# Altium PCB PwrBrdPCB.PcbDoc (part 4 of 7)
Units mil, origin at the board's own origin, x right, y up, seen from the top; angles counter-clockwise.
Board outline 8000 x 5500 mil, 4 copper layers (Top Layer, Internal 1, Internal 2, Bottom Layer), stack 61.834 mil thick; 682 components, 380 nets, 1899 pads, 766 vias.
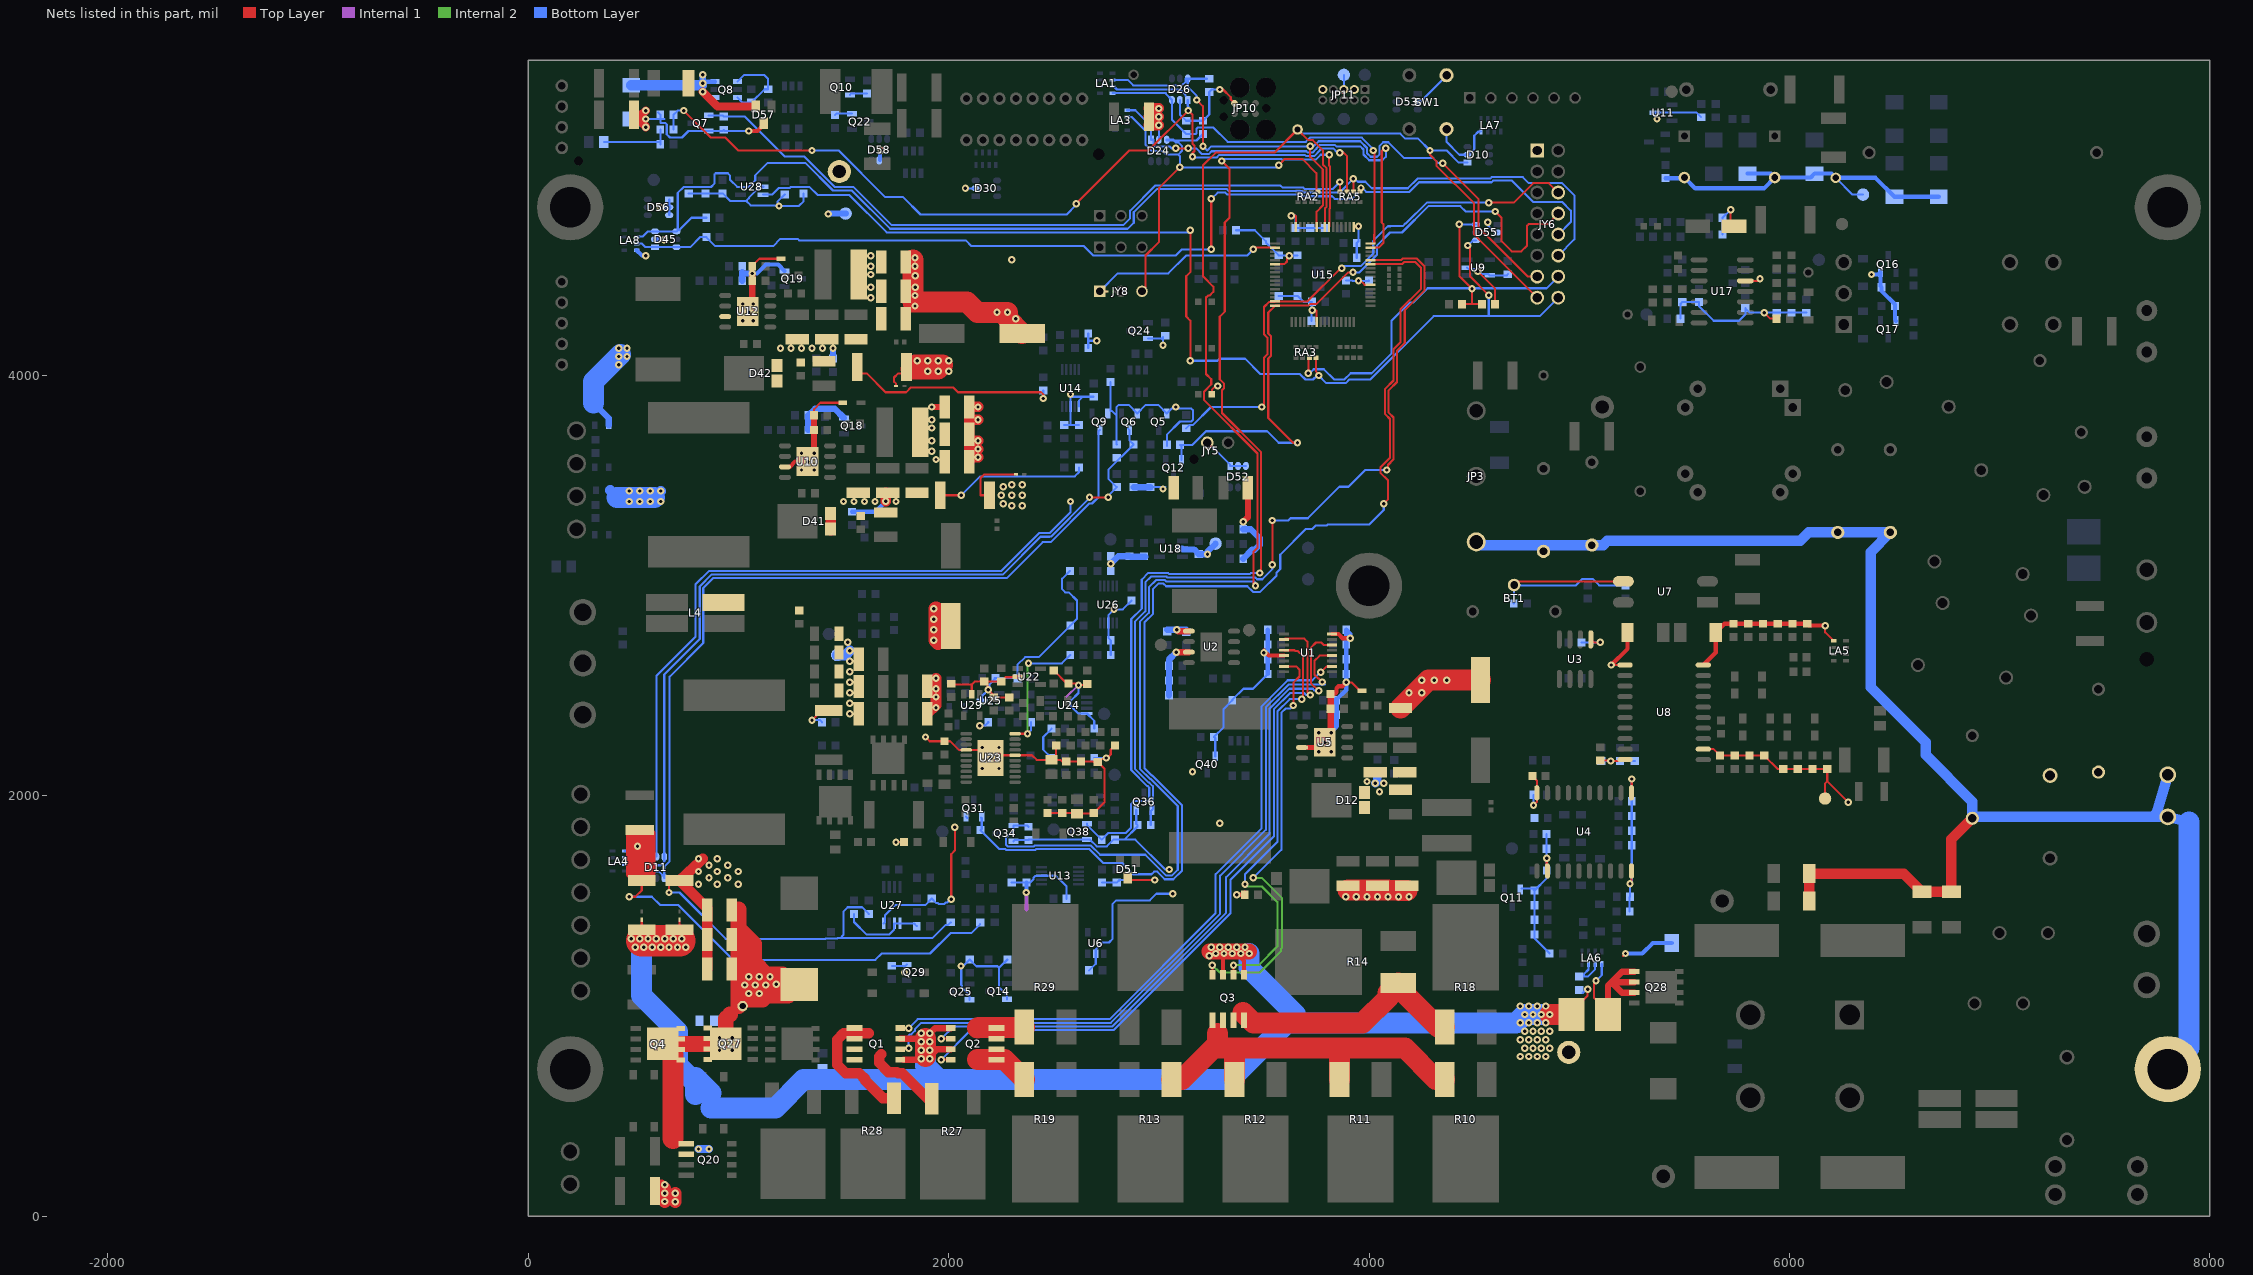
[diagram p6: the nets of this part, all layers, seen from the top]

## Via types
v1: diameter 35, hole 16, Top Layer to Bottom Layer, tented both sides, 409 vias
v2: diameter 35, hole 16, Top Layer to Bottom Layer, 348 vias
v3: diameter 35, hole 16, Top Layer to Bottom Layer, tented bottom, 5 vias
v4: diameter 60, hole 36, Top Layer to Bottom Layer, 2 vias
v5: diameter 65, hole 40.5, Top Layer to Bottom Layer, 2 vias

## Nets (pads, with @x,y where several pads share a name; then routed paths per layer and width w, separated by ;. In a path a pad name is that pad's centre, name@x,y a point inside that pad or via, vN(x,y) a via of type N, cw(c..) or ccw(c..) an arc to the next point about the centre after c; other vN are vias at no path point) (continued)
COMP.RX: JY6.8 Q12.2 R39.1 U15.64 | length 3302.8
  Top Layer w10: v1(3660,3680) 3638.28,3680 3520.5,3797.78 3520.5,4080.7 3533.5,4093.7 3533.5,4186.3 3520.5,4199.3 3520.5,4299.24 U15.64@3553.62,4332.36 3711.59,4332.36 3718.25,4339.03 3749.03,4339.03 3900.5,4490.5 v1(3924.03,4490.5) ; v1(4600,4780) 4630.78,4749.22 4630.78,4637.78 4678.06,4590.5 4724.27,4590.5 4751.35,4617.58 4751.35,4711.35 4760,4720 4850,4720 JY6.8@4900,4770
  Bottom Layer w10: Q12.2@3107.4,3599 3107.4,3664.1 R39.1@3101.5,3670 3160,3670 3224.5,3734.5 3515.5,3734.5 3570,3680 v1(3660,3680) v1@3650,3670 ; v1(3924.03,4490.5) 3920.5,4490.5 3920,4490 3954.04,4490 4037,4572.96 4037,4617 4100,4680 4156.8,4680 4282.09,4805.29 4434.71,4805.29 4460,4780 v1(4600,4780)
COMP.TX: JY6.6 R36.1 U15.63 | length 2592.7
  Top Layer w10: v1(3490,3850) 3500.5,3860.5 3500.5,4084.74 3516.5,4100.74 3516.5,4179.26 3500.5,4195.26 3500.5,4325.74 3525.03,4350.27 3551.84,4350.27 U15.63@3553.62,4352.05 3707.23,4352.05 3865.18,4510 v1(3870,4510) ; v1(4569.33,4822.27) 4688.81,4822.27 4781.41,4914.87 4855.13,4914.87 JY6.6@4900,4870
  Bottom Layer w10: R36.1@3130,3748.5 3145.29,3763.8 3161.7,3763.8 3247.9,3850 v1(3490,3850) ; v1(3870,4510) 3880,4520 3960,4520 4020,4580 4020,4640 4089.5,4709.5 4102.22,4709.5 4102.72,4710 4160,4710 4172.5,4722.5 4175.26,4722.5 4275.05,4822.29 v1(4569.33,4822.27)
COMP_D: C13.1 D11.1 D11.3 LA4.2 Q6.3 R34.2 R37.2 | length 4150.8
  Top Layer w10: v1(2670,3420) v1(2760,3420)
  Bottom Layer w10: LA4.2@459.53,1705.75 567.36,1705.75 D11.1@572.6,1710.98 572.6,1687.4 590,1670 630,1670 647.4,1687.4 D11.3@647.4,1710.98 647.4,2577.62 816,2746.22 816,2996 873.5,3053.5 1836.3,3053.5 1837.22,3052.58 2257.21,3052.58 2437.21,3232.58 2480,3232.58 2480.42,3233 2487.04,3233 v1@2672.02,3417.98 ; v1(2760,3420) 2760,3428.5 R37.2@2800,3468.5 2760,3508.5 2760,3551.5 R34.2@2880,3671.5 2860,3691.5 Q6.3@2860,3741 Q6.3@2852.5,3748.5
COMP_ENABLE: JY8.1 NT6.2 U15.50 | length 950.1
  Top Layer w10: JY8.1@2720,4400 NT6.2@2750.32,4400 ; v1(3450,4600) 3457.95,4607.95 U15.50@3553.62,4607.95
  Bottom Layer w10: JY8.1@2720,4400 2805.25,4485.25 3045.25,4485.25 3130.5,4570.5 3420.5,4570.5 v1(3450,4600)
COMP_T: D11.4 D11.6 LA4.3 Q9.3 | length 4086.3
  Bottom Layer w10: LA4.3@459.53,1674.25 507.36,1674.25 D11.6@572.6,1609.02 572.6,1622.6 590.5,1640.5 620.6,1640.5 D11.4@647.4,1613.7 ; D11.4@647.4,1609.02 D11.4@647.4,1613.7 ; Q9.3@2720,3741 2713.5,3734.5 2713.5,3421.78 2682.22,3390.5 2668.58,3390.5 2485.08,3207 2447.81,3207 2276.39,3035.58 1830.18,3035.58 1829.26,3036.5 880.54,3036.5 833,2988.96 833,2727.04 672.98,2567.02 672.98,1688.94 647.4,1663.36 D11.4@647.4,1613.7
CTL_COMP: D26.6 JY6.13 LA1.6 R83.2 U15.42 | length 3312.2
  Top Layer w10: v1(3180,5310) 3209.5,5280.5 3209.5,5090.5 v1(3210,5090) ; v1(3720,5090) 3720,5040 3780,4980 3780,4898.49 3781.06,4897.43 3781.06,4809.6 3750.47,4779.01 U15.42@3750.47,4706.38 ; v1(4350,5010) 4520,4840 4520,4706.18 4756.18,4470 JY6.13@4800,4470
  Bottom Layer w10: LA1.6@2779.53,5405.75 2851.93,5405.75 2877.67,5380 3110,5380 3127.4,5397.4 3127.4,5411.5 D26.6@3137.4,5411.5 ; D26.6@3137.4,5412.08 D26.6@3137.4,5411.5 ; v1(3180,5310) 3180,5330 3137.4,5372.6 D26.6@3137.4,5411.5 ; v1(3210,5090) 3230,5070 3250,5090 v1(3720,5090) 3735.96,5090 3759.96,5114 3958.32,5114 3990.5,5081.82 3990.5,5057.78 4007.78,5040.5 4038.31,5040.5 4050.5,5052.69 4050.5,5092.22 4067.78,5109.5 4092.22,5109.5 4168.22,5033.5 4306.3,5033.5 4329.8,5010 v1(4350,5010) ; R83.2@3230,5411.5 D26.6@3137.4,5411.5
CTL_PCOMP: D24.3 JY8.3 LA3.6 R84.2 RA2.1 | length 2186.4
  Top Layer w10: JY8.3@2920,4400 2936.36,4416.36 2936.36,4570.5 3000,4634.14 3000,4890 v1(3100,4990) ; v1(3570,5000) 3600,5030 3681.72,5030 3749.56,4962.16 3749.56,4883.28 RA2.1@3757.24,4875.59
  Bottom Layer w10: LA3.6@2850,5230 2870,5230 2937.02,5162.98 2937.02,5096.53 2966.04,5067.5 2980.24,5067.5 2980.74,5067 2981.86,5067 2982.36,5067.5 3017.64,5067.5 3034.64,5050.5 3048,5050.5 3092.22,5050.5 ; D24.3@3037.4,5117.8 3072.2,5117.8 ; D24.3@3037.4,5120.98 3069.02,5120.98 3072.2,5117.8 ; R84.2@3210,5148.5 3179.3,5117.8 3072.2,5117.8 ; v1(3570,5000) 3560,4990 v1(3100,4990) 3100,5042.72 3092.22,5050.5 ; 3072.2,5117.8 3080.5,5109.5 3092.22,5109.5 3109.5,5092.22 3109.5,5067.78 3092.22,5050.5
DC_OK: D24.1 LA3.5 U15.31 | length 2025.2
  Top Layer w10: v1(3080,5080) v1(3140,5080) ; U15.31@4006.38,4607.95 4045.91,4607.95 4067.95,4630 4067.95,4719.33 4060.5,4726.78 4060.5,5067.41 4073.09,5080 v1(4080,5080)
  Bottom Layer w10: LA3.5@2850,5261.5 2888.5,5261.5 2962.6,5187.4 D24.1@2962.6,5120.98 2974.42,5120.98 2974.42,5089.5 3050.5,5089.5 3060,5080 v1(3080,5080) ; v1(3140,5080) 3178.28,5080 3205.28,5053 3237.04,5053 3250.54,5066.5 3701.78,5066.5 3707.78,5060.5 3732.22,5060.5 3749.5,5077.78 3749.5,5079.5 3767,5097 3837.24,5097 3844.74,5089.5 3958.78,5089.5 3973.5,5074.78 3973.5,5050.74 4000.74,5023.5 4063.5,5023.5 4080,5040 v1(4080,5080)
DCBUS: C117.1 C119.1 C123.1 C124.1 C126.1 C127.1 C136.1 C137.1 C138.1 L2.1 L16.1 L45.1 MECH5.1 Q4.D Q20.5 Q20.6 Q27.D TP27.1 | length 2746.6
  Top Layer w30: v2(1920,3850) C124.1@1981.93,3850
  Top Layer w75: Q4.D@690,770 Q4.D@640,820 Q27.D@940,820 940,940 960,960 ; TP27.1@1000,1000 1000,1140 1000,1370 ; 1000,1460 1000,1370 ; 1000,1370 1075,1295 1075,1208.46 ; 1075,1075 1075,1150 ; 1075,1075 1103.46,1103.46 v2(1180,1103.46) ; 1075,1075 1030,1030 1114.69,1030 1134.97,1050.28 1236.82,1050.28 L2.1@1290,1103.46 L2.1@1256.54,1103.46 ; 1075,1150 1133.46,1150 ; 1075,1150 1075,1208.46 ; 1075,1208.46 1133.46,1150 ; 1133.46,1150 1210,1150 L2.1@1256.54,1103.46 ; 1133.46,1150 1146.73,1136.73 v2(1180,1103.46) ; v2(1180,1103.46) L2.1@1256.54,1103.46
  Top Layer w100: 690,370.55 Q4.D@690,770
  Bottom Layer w40: v2(810,320) v2(860,320)
  other v2: 910,790 970,790 910,850 970,850 1050,1060 1100,1060 1030,1100 1080,1100 1130,1100 1050,1140 1100,1140 1150,1140 1940,3600 1920,3640 1920,3690 1920,3750 1920,3790 1630,4370 1630,4420 1630,4480 1630,4520 1630,4570
DCMON.N3: D13.A LA6.1 Q28.S R25.1 | length 1054
  Top Layer w10: v1(5080,1120) 5070,1110 5070,1040 R25.1@5136.61,973.39 ; R25.1@5136.61,960 R25.1@5136.61,966.69 ; v1@5208,1238 v1(5220,1250)
  Top Layer w30: R25.1@5136.61,966.69 5136.61,973.39 5136.61,1096.61 5153.55,1113.55 ; Q28.S@5261.63,1063.55 5203.55,1063.55 5153.55,1113.55 ; Q28.S@5261.63,1113.55 5153.55,1113.55 ; Q28.S@5261.63,1163.55 5203.55,1163.55 5153.55,1113.55
  Bottom Layer w10: v1(5080,1120) 5107.24,1147.24 LA6.1@5107.24,1200.47
  Bottom Layer w20: v1(5220,1250) 5300,1250 5350,1300 D13.A@5440,1300
DCMON.N4: LA6.2 LA6.3 NT1.1 | length 163.2
  Bottom Layer w10: LA6.3@5044.25,1200.47 5044.25,1174.25 5021.84,1151.84 5021.84,1140 5040,1140 5075.75,1175.75 LA6.2@5075.75,1200.47
DR0: Q1.5 Q1.6 R28.1 | length 620.7
  Top Layer w50: 1620,870 1500,870 1470,840 1470,720 1510,680 1575.25,680 1604.5,650.75 1604.5,645.5 1687.5,562.5 R28.1@1740,562.5
DR1: Q1.7 Q1.8 R27.2 | length 364.6
  Top Layer w50: 1680,770 1670,760 1670,730 1713.78,686.22 1753.78,686.22 1760,680 1780,680 1900,560 R27.2@1920,560
DR2: Q2.7 Q2.8 R29.1 | length 224.1
  Top Layer w100: 2137.6,895 2141.61,899.02 R29.1@2360,899.02
DR3: Q2.5 Q2.6 R19.2 | length 261.3
  Top Layer w100: 2137.6,745 Q2.5@2227.6,745 2265.98,745 R19.2@2360,650.98
DR4: Q3.7 Q3.8 R14.1 R18.1 | length 1169.4
  Top Layer w100: 3400,970 3450,920 3970,920 4091.44,1041.44 4091.44,1062.5 R14.1@4138.94,1110 4138.94,1091.06 4328.98,901.02 R18.1@4360,901.02
DR5: Q3.5 Q3.6 R10.2 R11.2 R12.2 R13.1 | length 1773.9
  Top Layer w100: R13.1@3060,650.98 3110.98,650.98 3260,800 ; 3280,870 3280,800 3350,800 3360,790 ; R12.2@3360,650.98 3360,790 ; R11.2@3860,650.98 3860,790 3850,800 ; R10.2@4360,650.98 4319.02,650.98 4170,800 3850,800 ; 3360,790 3370,800 3850,800
FAN_CTL: D26.3 LA1.8 R82.2 U15.32 | length 1932.1
  Top Layer w10: U15.32@4006.38,4627.64 4024.09,4627.64 4025,4628.54 4025,4670.96 4025.56,4671.52 4025.56,5057.68 4020,5063.24 v1(4020,5070)
  Bottom Layer w10: LA1.8@2779.53,5342.76 3029.96,5342.76 ; 3032.72,5342.76 3029.96,5342.76 ; v1(4020,5070) 4013.16,5076.84 4013.16,5083.2 3965.36,5131 3719.28,5131 3699.53,5111.25 3327.16,5111.25 3259.2,5179.2 3185.34,5179.2 3178.31,5172.18 3178.31,5151.36 3175.46,5148.5 R82.2@3130,5148.5 3062.6,5215.9 D26.3@3062.6,5310.12 3029.96,5342.76
FAN_DRAIN: D25.K D57.2 F5.1 Q8.4 Q8.6 | length 778.5
  Top Layer w40: v1(830,5350) 900.63,5279.37 D57.2@1082.6,5279.37
  Bottom Layer w20: v1@825,5380 v1@835,5390 ; v1@830,5340.36 847.76,5322.6 Q8.4@868.55,5322.6 ; v1(830,5390) v1@835,5390 ; Q8.6@888.55,5397.4 847.4,5397.4 840,5390 v1@835,5390
  Bottom Layer w30: v1(830,5390) v1(830,5430)
  Bottom Layer w50: D25.K@490,5380 v1@825,5380
FAN_GATE: Q8.1 Q8.3 R4.1 R76.1 | length 400.1
  Bottom Layer w10: Q8.3@994.85,5322.6 1018.95,5298.5 R4.1@1061.7,5298.5 1124.7,5361.5 R76.1@1141.7,5361.5 1141.7,5410 1121.7,5430 1027.45,5430 Q8.1@994.85,5397.4
FAN_LOCKED: L12.1 R78.1 R79.2 | length 338.5
  Bottom Layer w10: L12.1@360,5110 R78.1@628.5,5110 ; R78.1@628.5,5100 R79.2@628.5,5170
FAN_ON: Q7.1 R139.1 RA5.4 | length 3383
  Top Layer w10: v1(3860,4920) 3861.38,4918.62 3861.38,4876.97 RA5.4@3862.76,4875.59
  Bottom Layer w10: Q7.1@859,5237.4 924.1,5237.4 R139.1@930,5231.5 1030.43,5231.5 1220.43,5041.5 1312.55,5041.5 1457.04,4897 1547.04,4897 1729.16,4714.88 2830.74,4714.88 2863.5,4747.64 2863.5,4783.4 2983.6,4903.5 3578.42,4903.5 3587.42,4894.5 3685.7,4894.5 3693.7,4886.5 3826.5,4886.5 v1(3860,4920)
FG1: C44.1 D26.1 LA1.7 R79.1 RA5.3 | length 4587.5
  Top Layer w10: v1(740,5260) 868.31,5131.69 937.13,5131.69 998.81,5070 v1(1350,5070) ; v1(2608,4816.5) 2608,4818 2860,5070 2950,5070 v1(3140,5260) 3160,5240 3160,5101.72 3169.5,5092.22 3169.5,5067.78 3160,5058.28 v1(3160,5040) v1@3153,5047 ; v1(3860,5060) 3878.5,5060 3894.25,5044.25 RA5.3@3894.25,4875.59
  Bottom Layer w10: R79.1@691.5,5170 C44.1@691.5,5240 711.5,5260 v1(740,5260) ; v1(1350,5070) 1476.56,5070 1698.28,4848.28 1783.44,4848.28 1866.22,4765.5 2561.5,4765.5 2608,4812 v1(2608,4816.5) ; LA1.7@2779.53,5374.25 2786.66,5374.25 2800.91,5360 3101.1,5360 3127.4,5333.7 D26.1@3127.4,5329.02 ; D26.1@3137.4,5310.12 3137.4,5282.83 3140,5280.23 v1(3140,5260) ; v1(3160,5040) 3164,5036 3274.28,5036 3287.78,5049.5 3694.74,5049.5 3700.74,5043.5 3739.26,5043.5 3766.5,5070.74 3766.5,5072.46 3774.04,5080 3830.2,5080 3847.2,5063 3877,5063 3870,5056 3866,5060 v1(3860,5060)
GND: C1.2 C2.1 C30.2 C39.2 C41.1 C42.1 C70.2 C71.1 GDT2.2 GDT4.2 GDT5.2 JP2.1 JP3.1 Z2.0 | length 7335.4
  Top Layer w50: C2.1@6094.65,1520 C1.2@6094.65,1630 6544.65,1630 C71.1@6630,1544.65 C70.2@6770,1544.65 6770,1793.15 GDT4.2@6870,1893.15
  Bottom Layer w50: JP3.1@4510,3208 4524.85,3193.15 C42.1@5060,3193.15 5113.15,3193.15 5133.57,3213.57 6052.27,3213.57 6091.86,3253.15 C41.1@6230,3253.15 C30.2@6480,3253.15 6386.48,3159.63 6386.48,2515.71 6647.5,2254.69 6647.5,2194.69 6870,1972.19 GDT4.2@6870,1893.15 ; GDT4.2@6890,1900 7740.74,1900 ; JP2.1@7790,2110 JP2.1@7800,2100 7745.52,1916.14 7744.83,1913.79 ; Z2.0@7800,700 Z2.0@7900,800 ; 7900,1875 JP2.1@7800,1900 ; 7740.74,1900 JP2.1@7800,1900 ; 7740.74,1900 7744.83,1913.79 ; 7740.74,1900 7743.12,1911.64 7743.63,1914.09 7744.83,1913.79 ; 7744.83,1913.79 JP2.1@7800,1900
  Bottom Layer w100: Z2.0@7900,800 7900,1875
GND_AUX1: C91.2 C92.2 C94.2 C95.2 C96.2 C97.2 C116.- C117.2 C123.2 C124.2 C125.2 D23.A D41.A1 D41.A2 L41.1 Q18.2 R115.2 R116.2 R117.2 R118.2 R132.1 U10.7 U10.9 | length 2825.6
  Top Layer w10: R117.2@1360,3810 1360,3840 1390,3870 D23.A@1496.69,3870 ; R118.2@1960,3430 v1(2060,3430)
  Top Layer w20: U10.7@1221.34,3565 1245,3565 1270,3590 U10.9@1328.62,3590
  Top Layer w30: U10.9@1328.62,3590 1360,3621.38 R116.2@1360,3740 R117.2@1360,3810
  Top Layer w50: D41.A1@1438.19,3263.78 D41.A1@1438.19,3270 D41.A2@1438.19,3336.22 ; v2(1701.5,3401.5) C125.2@1701.5,3441.93 ; C123.2@2098.07,3590 C123.2@2098.07,3610 ; v2(2140,3610) C123.2@2098.07,3610 ; v2(2140,3650) 2098.07,3650 ; v2(2140,3690) C117.2@2098.07,3690 ; v2(2140,3790) 2098.07,3790 ; v2(2140,3850) C124.2@2098.07,3850 2098.07,3790 ; C123.2@2098.07,3610 2098.07,3650 ; 2098.07,3650 C117.2@2098.07,3690 ; C117.2@2098.07,3690 C117.2@2098.07,3720 2098.07,3790
  Top Layer w70: v2@1940,2890 1940,2740 1950,2730 2010,2790 C116.-@2010,2808.11
  Bottom Layer w10: v1(2060,3430) 2150,3520 2600,3520 2620,3540 R132.1@2620,3561.38
  Bottom Layer w20: R115.2@1540,3351.5 1651.5,3351.5 v2(1701.5,3401.5)
  Bottom Layer w30: C96.2@1332.99,3740 C97.2@1332.99,3810 1364.72,3841.72 1458.17,3841.72 Q18.2@1502.5,3797.4
  Bottom Layer w50: L41.1@390,3452.87 422.87,3420 ; 600,3420 v2(630,3450)
  Bottom Layer w100: 422.87,3420 600,3420
  other v2: 1930,2740 1930,2790 1930,2840 1930,2890 480,3400 530,3400 580,3400 630,3400 1500,3400 1550,3400 1600,3400 1650,3400 1750,3400 480,3450 530,3450 580,3450 1300,3550 1360,3550 1330,3590 1300,3630 1360,3630
GND_AUX2: C99.2 C100.2 C102.2 C103.2 C104.2 C105.2 C118.- C119.2 C126.2 C127.2 C128.2 D42.A1 D42.A2 D49.A L44.1 Q19.2 R124.2 R125.2 R126.2 R127.2 R134.1 U12.7 U12.9 | length 2929.9
  Top Layer w10: R126.2@1065.63,4520 1065.63,4520.98 1099.65,4555 D49.A@1202.49,4555 ; R127.2@1560,4010 1610,4010 1700,3920 1797.67,3920 1819.99,3942.32 2022.06,3942.32 2044.37,3920 2440,3920 2450,3910 v1(2450,3890)
  Top Layer w30: U12.9@1019.41,4280 U12.9@1044.41,4305 1065.63,4326.22 R125.2@1065.63,4450 v1(1065.63,4485)
  Top Layer w100: v2@1830,4550 1830,4400 1830,4350 2088.21,4350 2138.21,4300 v2(2230,4300) v2(2280,4300) 2280,4270 C118.-@2350,4200
  Bottom Layer w10: v1(2450,3890) R134.1@2450,3928.5
  Bottom Layer w20: v1(1065.63,4485) 1088.2,4485 1130.4,4527.2 1189.33,4527.2 Q19.2@1219.13,4497.4
  Bottom Layer w30: 310,3870 383.46,3796.54 L44.1@383.46,3762.87 ; C104.2@1018.62,4450 1018.62,4491.38 1025,4485 v1(1065.63,4485) ; R124.2@1450,4080 v2(1450,4130)
  Bottom Layer w100: 310,3870 310,3970 v3(430,4090) v3@440,4100
  other v2: 1200,4130 1250,4130 1300,4130 1350,4130 1400,4130 1020,4260 1070,4260 2320,4270 1050,4300 1840,4330 1020,4340 1070,4340 1840,4380 1841.5,4420 1841.5,4474.99 1840,4520 1840,4560
  other v3: 430,4050 470,4090 430,4130 470,4130
GND_AUX3: C133.2 C134.2 C135.2 C136.2 C137.2 C138.2 C139.2 C140.2 C141.2 C142.2 C143.2 C144.2 C145.2 C146.2 C148.2 C149.2 C150.2 C151.2 C152.2 C154.2 C155.2 C156.2 C157.2 C159.2 C160.2 C163.2 C164.2 C166.2 C167.2 C180.2 C183.2 C184.2 L4.1 Q31.2 R130.1 R150.2 R160.2 R167.2 R168.2 R172.2 R175.2 R178.2 R187.2 R195.2 R197.2 R199.1 R202.2 R203.1 R205.2 R207.1 TP39.1 U22.2 U23.6 U23.14 U23.21 U24.4 U25.3 U27.4 U29.2 | length 7625.7
  Top Layer w10: v1(670,1540) 670,1580 687.13,1597.13 R160.2@720,1597.13 ; v1(1350,2360) 1405.75,2415.75 R172.2@1430,2415.75 ; v1(1750,1780) C159.2@1788.5,1780 ; v1(1890,2280) 1910,2260 C133.2@1980,2260 2007.46,2260 2048.68,2218.78 U23.14@2083.86,2218.78 2161.61,2218.78 v1(2200,2180.39) 2212.79,2193.19 U23.6@2316.14,2193.19 2396.81,2193.19 2418.5,2171.5 2511.49,2171.5 R178.2@2511.49,2240 ; C183.2@2000,2532.99 2002.99,2530 2110,2530 ; v1(2012.78,1508.78) 2012.78,1722.78 2030,1740 v1(2030,1850) ; U29.2@2110,2482.93 2110,2530 ; C134.2@2180,2543.9 2210,2543.9 ; 2214.78,2543.68 2215,2543.9 C135.2@2250,2543.9 2270.51,2564.41 U22.2@2316.85,2564.41 ; C184.2@2288.8,2468.74 R150.2@2214.78,2468.74 2214.78,2478.5 v1(2188.5,2504.78) 2184.68,2508.6 2184.68,2529.8 2170.98,2543.5 C134.2@2170,2543.5 2123.5,2543.5 2110,2530 ; R167.2@2470,1918.5 C155.2@2540,1918.5 2607.05,1918.5 C156.2@2610,1915.55 2687.05,1915.55 R197.2@2690,1918.5 2741.69,1970.19 2741.69,2129.81 R187.2@2710,2161.5 2723.7,2175.2 2738.43,2175.2 2743.23,2180 v1(2750,2180) 2754.49,2180 2771.5,2197.01 2771.5,2220 2776.81,2225.32 2776.81,2226.3 2790.51,2240 C160.2@2791.49,2240 ; C154.2@2470,2171.5 C154.2@2490,2171.5 2531.5,2171.5 2540,2162.99 R168.2@2560,2162.99 2610,2162.99 C157.2@2630,2162.99 2688.5,2162.99 2690,2161.5 ; C144.2@2500,2596.89 2562.99,2533.9 C145.2@2570,2533.9 2610.52,2533.9 v1(2617.91,2526.5) 2653.59,2526.5 C146.2@2660,2532.91
  Top Layer w50: 830,1700 819.33,1690.02 789.4,1662.03 R160.2@720,1597.13 851.93,1465.2 C138.2@851.93,1456.54 C137.2@851.93,1316.54 C136.2@851.93,1176.54 ; C140.2@1898.07,2390 1940,2431.93 v2(1940,2470) v2(1940,2510) v2(1940,2560)
  Internal 1 w10: 2560,2470 2616.5,2526.5 v1(2617.91,2526.5)
  Bottom Layer w10: v1(670,1540) 720,1540 940,1320 1414.64,1320 1415.34,1320.7 1470,1320.7 1472.3,1323 1484.72,1323 ; v1(1350,2360) 1388.5,2360 R175.2@1398.5,2350 ; R207.1@1620,1438.5 1588.5,1470 1520,1470 1499.5,1449.5 1499.5,1337.78 1484.72,1323 ; U27.4@1691.61,1393.39 1697.33,1399.1 1697.33,1431.37 1745.96,1480 1888.5,1480 R205.2@1920,1511.5 1941.5,1490 1948.28,1490 1953.11,1485.17 1978.31,1485.17 1985.34,1492.2 1993.92,1492.2 1999.5,1497.78 1999.5,1506.35 2005.93,1512.78 2009.93,1508.78 v1(2012.78,1508.78) ; R130.1@2010,1398.5 1996.3,1384.8 1984.8,1384.8 1923,1323 1484.72,1323 ; Q31.2@2082.6,1901 Q31.2@2088.5,1895.1 ; v1(2147.5,2333.69) 2149.12,2335.31 2174.8,2335.31 2188.5,2349.02 R195.2@2188.5,2350 ; U25.3@2158.66,2451.5 2158.66,2474.94 v1(2188.5,2504.78) 2193.29,2509.57 2193.29,2529.31 2222.99,2559.02 R202.2@2222.99,2560 ; R202.2@2218.28,2560 R202.2@2222.99,2560 ; C166.2@2490,2180 2450,2220 2450,2280 C167.2@2490,2320 ; R203.1@2577.01,3070 2540,3032.99 2540,2983.15 2554.83,2968.32 2571.68,2968.32 2610.8,2929.2 2610.8,2842.29 R199.1@2578.5,2810 2428.5,2660 2363.92,2660 2327.01,2623.09 C180.2@2327.01,2560 R202.2@2222.99,2560 ; v1@2616.88,2527.53 v1(2617.91,2526.5) 2617.91,2489.63 2580.5,2452.22 2580.5,2427.78 2615.55,2392.73 2657,2392.73 U24.4@2658.11,2391.62 2692.99,2356.73 C164.2@2692.99,2320 ; C163.2@2692.99,2180 v1(2750,2180)
  Bottom Layer w50: TP39.1@1470,2670 1510,2670 v2(1530,2690)
  other v1: 2160,2130 2240,2130 2160,2230 2240,2230
  other v2: 810,1580 900,1580 1000,1580 860,1610 950,1610 810,1640 900,1640 1000,1640 860,1670 950,1670 810,1700 900,1700 1530,2390 1940,2420 1530,2440 1530,2490 1530,2540 1530,2590 1530,2640 1520,2730
GND_COMP: L50.1 LA4.1 R128.1 R140.2 | length 2824.3
  Top Layer w10: v1(480,1520) 510,1520 540,1550 R140.2@540,1597.13
  Top Layer w50: 490,1810 490,1630 500,1620 517.13,1620 R140.2@530,1607.13 ; R140.2@530,1607.13 R140.2@540,1597.13 580,1637.13 580,1820 562.87,1837.13 L50.1@530,1837.13 R140.2@530,1607.13
  Bottom Layer w10: LA4.1@459.53,1737.24 497.24,1737.24 v1(520,1760) ; v1(480,1520) 588.28,1520 627.78,1480.5 713.54,1480.5 974.04,1220 1651.72,1220 1681.72,1250 1911.72,1250 2008.72,1347 2107,1347 R128.1@2150,1390
GND_ISO: BT1.- C3.2 C4.2 C5.2 C6.1 C7.2 C8.2 C9.2 C10.1 C11.1 C12.1 C13.2 C14.2 C15.2 C16.2 C18.2 C19.2 C20.2 C21.2 C22.2 C23.2 C24.2 C25.2 C26.2 C27.2 C28.2 C29.2 C43.2 C44.2 C45.2 C46.2 C47.2 C48.2 C49.2 C50.2 C53.2 C54.2 C55.2 C56.2 C57.2 C58.2 C59.2 C60.2 C61.2 C64.2 C65.2 C67.2 C68.1 C69.1 C73.1 C76.1 C85.2 C87.2 C88.2 C89.2 C106.2 C107.2 C108.2 C109.2 C110.2 C111.2 C112.2 C113.2 C114.2 C115.2 C120.- C121.2 C122.2 C129.2 C130.2 C131.2 C132.2 C170.2 C171.2 C172.2 C173.2 C174.2 C177.2 C181.2 C182.2 C185.2 C186.2 C187.2 C188.2 D10.2 D11.2 D12.A1 D12.A2 D24.2 D25.A D26.2 D30.2 D31.K D45.2 D50.A D51.3 D52.1 D52.2 D52.3 D53.2 D55.2 D56.1 D56.2 D56.3 D57.3 D58.2 JP10.5 JP11.3 JP11.5 JP11.9 JY5.1 JY6.1 L15.1 L33.2 L48.1 LA7.8 LA8.8 MECH2.2 MECH5.2 NT1.2 NT2.1 NT3.1 NT4.1 NT5.1 Q1.1 Q1.3 Q2.1 Q2.3 Q3.1 Q3.3 Q5.2 Q6.2 Q7.2 Q9.2 Q10.2 Q11.2 Q14.2 Q22.2 Q24.2 Q25.2 Q29.2 Q34.2 Q36.2 Q38.2 Q40.2 R1.2 R20.2 R21.2 R22.1 R23.1 R24.1 R25.2 R30.2 R31.2 R33.2 R35.1 R38.2 R39.2 R46.2 R47.1 R48.2 R50.2 R73.1 R80.1 R82.1 R83.1 R84.1 R90.1 R98.2 R118.1 R127.1 R139.2 R140.1 R145.1 R146.1 R151.1 R152.1 R155.1 R156.1 R158.1 R160.1 R173.2 R181.1 R186.1 R196.1 SW1.3 SW1.4 TP5.1 TP10.1 TP19.1 TP20.1 TP30.1 U1.8 U1.13 U2.1 U2.3 U3.5 U4.2 U4.10 U4.11 U4.20 U5.7 U5.9 U6.2 U7.3 U8.11 U8.20 U9.2 U9.5 U13.3 U14.1 U14.3 U15.7 U15.22 U15.33 U15.47 U15.54 U18.2 U26.3 U28.2 | length 30614.4
  Top Layer w10: L15.1@502.87,5240 522.87,5220 v1(560,5220) ; R140.1@540,1362.87 540,1400 ; R160.1@720,1362.87 720,1400 ; D57.3@1120,5192.76 D57.3@1120,5200.63 ; NT3.1@1750.32,3950 1750.32,3959.68 1740,3970 1740,3990 1760,4010 R127.1@1794.25,4010 ; R118.1@2194.25,3430 2152,3430 2152,3512 2168.75,3528.75 NT2.1@2320.32,3528.75 ; D51.3@2852.6,1610.63 2863.23,1600 v1(2980,1600) ; D31.K@3252.48,3910 3252.48,3932.48 3270,3950 v1(3280,3950) ; v1(3290,5360) 3305.61,5360 3342.25,5323.36 3342.25,5312.75 JP10.5@3360,5295 ; U15.54@3553.62,4529.21 3597.49,4529.21 3610,4541.72 3610,4566.5 3613.5,4570 v1(3620,4570) ; v1(3630,4760) 3650,4760 3652.05,4757.95 U15.47@3652.05,4706.38 ; v1(3730.47,4309.53) 3750.47,4309.53 U15.7@3750.47,4253.62 ; v1(3891.5,2540) 3916.85,2540 3956.85,2500 D50.A@3966.69,2500 ; U15.33@3927.64,4706.38 3953.62,4706.38 v1(3950,4710) ; v1(3950,4450) 3960,4450 3979.21,4430.79 U15.22@4006.38,4430.79 ; v2(4517.68,4495.3) 4600,4412.99 R152.1@4600,4339.03 ; BT1.-@4690,3002.99 4707.01,3020 U7.3@5210,3020 ; C12.1@4777.01,2094.64 4798.5,2073.15 U4.20@4798.5,2014.65 4798.5,1972.13 v1(4782.52,1956.14) ; v1(4845.51,1703.15) 4845.51,1645.59 U4.2@4848.5,1642.6 ; R25.2@4963.39,960 4963.39,973.39 5040,1050 v1(5040,1080) ; U3.5@5055,2744.49 5069.49,2730 v1(5100,2730) ; C68.1@5100,2168.5 5147.24,2168.5 v1(5150,2165.75) 5211.57,2165.75 U8.20@5218.07,2172.24 ; v1(5152.24,2622.24) U8.11@5218.07,2622.24 ; v1(5241.5,1582.13) 5248.5,1589.14 U4.10@5248.5,1642.6 ; U4.11@5248.5,2014.65 U4.11@5254.02,2020.16 ; U4.11@5250,2025.51 v1(5250,2080)
  Top Layer w20: v1(1048.75,5163.05) 1090.29,5163.05 D57.3@1120,5192.76 ; Q3.3@3305,1148.94 3305,1225 3320,1240 v2@3350,1240 ; v2@3350,1260 v2(3350,1250) v2@3350,1240 ; v1(3370,1530) 3398.5,1530 R80.1@3408.5,1540 ; Q3.1@3405,1148.94 3405,1215 3380,1240 v2@3350,1240 ; v1@3500,2690 3522.8,2667.2 U1.13@3595.83,2667.2 ; R50.2@3817.28,2485 3836.49,2485 3844.58,2493.08 3844.58,2511.72 3854.53,2521.68 3873.18,2521.68 v1(3891.5,2540) ; U1.8@3824.17,2769.57 3854.12,2769.57 3873.69,2750 v1(3910,2750) ; v1(5152.24,2622.24) 5229.45,2699.45 C85.2@5229.45,2777.24
  Top Layer w23: U5.7@3710,2230 U5.9@3763.78,2230
  Top Layer w30: v2@632.87,150 L48.1@602.87,120 612.87,110 v2(650,110) 650,91.44 ; v2(650,70) 650.62,69.38 v2(699.38,69.38) v2@700,70 ; v2@650,72.87 650,91.44 ; 651.44,90 650,91.44 ; Q1.3@1768.94,845 1885,845 ; Q1.1@1785,745 1895,745 v2@1880,760 ; v2@1880,840 1885,845 ; 1890,845 1885,845 ; v2@1910,760 1945,795 Q2.3@2011.06,795 ; Q2.1@2011.06,895 1935,895 v2(1910,870) 1885,845 ; v1(3083.5,2683.5) U2.3@3142.72,2683.5 ; v1(3085,2790) 3091.5,2783.5 U2.1@3142.72,2783.5 ; v1(3401.5,3303.51) 3423.87,3325.87 C48.2@3423.87,3465.52 ; U5.9@3763.78,2230 v2(3788.78,2255) 3817.28,2283.5 R48.2@3817.28,2415 R50.2@3817.28,2485
  Top Layer w40: L15.1@502.87,5240 540,5240 v1(560,5260) ; L15.1@522.87,5220 560,5182.87 v1(560,5180)
  Top Layer w50: v2@540,1310 R140.1@540,1362.87 ; L48.1@612.87,110 612.87,87.13 632.87,87.13 ; v2@632.87,150 v2@650,132.87 ; v2@720,1310 R160.1@720,1362.87 ; L33.2@2952.87,5190 v1(3000,5190) ; L33.2@2952.87,5230 v1(3000,5230) ; L33.2@2952.87,5270 v1(3000,5270)
  Top Layer w60: 632.87,87.13 v2(650,70) ; v2(650,110) v2@650,132.87 ; v2@700,70 v2(700,110)
  Top Layer w75: 3240,1260 3350,1260 v2@3430,1260
  Top Layer w100: 1890,760 1890,845 ; C121.2@3900,1551.93 4040,1551.93 4042.8,1552.33 4090.54,1551.52 4140.52,1550.67 4179.63,1550.01 C130.2@4180,1550 ; C132.2@4150,2418.07 4282.87,2550.94 C120.-@4530,2550.94 ; v2(4860,960) R25.2@4963.39,960 ; R127.1@1820,4030 1950,4030 1970,4050 1840,4050 R127.1@1820,4030
  Top Layer w150: v2@540,1310 v2@720,1310
  Internal 1 w20: 2370,1460 v1(2370,1540)
  Bottom Layer w10: D25.A@490,5220 v1(560,5220) 648.5,5220 ; 541.69,4570 v1(560,4570) ; D11.2@610,1710.98 610,2570 796.22,2756.22 796.22,3006.22 860.5,3070.5 1843.34,3070.5 1843.84,3070 2250,3070 2430,3250 2480,3250 2580,3350 v1(2580,3400) ; C44.2@618.5,5250 C44.2@628.5,5240 628.5,5201.69 652.18,5201.69 659.2,5194.66 659.2,5146.93 674.45,5131.69 731.69,5131.69 762.6,5162.6 Q7.2@859,5162.6 924.1,5162.6 R139.2@930,5168.5 935.45,5163.05 v1(1048.75,5163.05) ; v1@645.03,4647.8 v1(647.82,4645) ; D56.3@670.98,4762.6 D56.2@670.98,4800 D56.1@670.98,4837.4 ; C187.2@763.99,4865.88 C188.2@843.99,4865.88 C186.2@923.99,4865.88 924.98,4865.88 960.86,4830 1037.4,4830 ; U28.2@1117.98,4897.38 1102.98,4897.38 1088.62,4883.02 1087.06,4883.02 1050,4845.96 1050,4842.6 1037.4,4830 ; v1@1185.52,4813.74 1185.52,4825.83 C122.2@1220.63,4860.94 ; C185.2@1310,4866.34 1310,4827.91 1287.91,4805.83 v1(1193.43,4805.83) 1190.36,4808.89 1058.51,4808.89 1037.4,4830 ; R1.2@1460,5239.45 1465.9,5245.35 Q22.2@1541,5245.35 ; Q10.2@1530.49,5334.46 1536.4,5340.36 R47.1@1611.49,5340.36 ; D58.2@1669.99,5022.85 D58.2@1673.28,5026.13 ; v1@1673.28,5057.22 1680,5063.94 v1(1680,5070.71) ; R158.1@1730,1191.5 Q29.2@1795.1,1191.5 ; v1(1790,1160) 1790,1186.4 Q29.2@1795.1,1191.5 ; Q29.2@1801,1197.4 Q29.2@1795.1,1191.5 ; v1(2059.23,1190.77) 2059.23,1182.26 2060,1181.5 2060,1100 2064.38,1095.62 2064.38,1087.33 2100,1051.71 Q25.2@2100,1030 ; v1@2064.25,1185.75 R156.1@2100,1221.5 2132.29,1189.2 2232.29,1189.2 2240,1181.5 ; v1(2080,4890) D30.2@2129.02,4890 ; Q14.2@2278,1032.6 2278,1052 2240,1090 2240,1181.5 ; R155.1@2280,1221.5 2240,1181.5 ; C110.2@2300,1587.01 C109.2@2370,1587.01 2387.01,1587.01 2403.83,1603.83 2403.83,1611.19 2410.86,1618.22 2440.62,1618.22 U13.3@2442.4,1620 2510,1620 2561.5,1568.5 C106.2@2561.5,1510 ; Q34.2@2309,1784.1 2314.9,1790 R181.1@2380,1790 2382.6,1792.6 Q38.2@2659,1792.6 2672.04,1792.6 2704.83,1759.81 2752.17,1759.81 2783.86,1791.5 R196.1@2791.49,1791.5 2835.54,1791.5 ; C114.2@2550,3764.37 C115.2@2620,3764.37 ; 2580,3770 U14.3@2580,3852.4 2580,3890 ; v1(2580,3910) 2580,3907.01 2588.5,3898.5 2638.5,3898.5 ; U14.1@2619.37,3852.4 2619.37,3879.37 2638.5,3898.5 ; C113.2@2664.37,4130 2664.37,4165 ; C112.2@2664.37,4200 2664.37,4165 ; C29.2@2668.5,1170 2700,1201.5 U6.2@2700,1249 2700,1270 2732.5,1302.5 2763.01,1302.5 2780,1319.49 2780,1485.96 2797.04,1503 2957.04,1503 2988.19,1534.15 v1(3065.86,1534.15) ; C111.2@2690,3898.5 2638.5,3898.5 ; v1(2705,4165) 2664.37,4165 ; C108.2@2730,1587.01 C107.2@2800,1587.01 2812.99,1600 v1(2980,1600) ; R31.2@2770,3968.5 2770,3831.6 2776.5,3831.6 2798.1,3810 ; C174.2@2771.5,2670 C173.2@2771.5,2740 2760,2751.5 U26.3@2760,2822.4 2760,2860 v1(2787.01,2887.01) 2828.51,2887.01 C170.2@2870,2928.5 ; C13.2@2800,3671.5 2798.1,3673.39 2798.1,3810 ; R186.1@2892.6,1867.4 Q36.2@2892.6,1932.5 ; R186.1@2898.5,1861.5 2898.5,1854.46 2835.54,1791.5 ; Q24.2@2949,4175.75 3014.1,4175.75 3020,4181.65 v1(3020,4143.15) ; C14.2@2960,3468.5 v1@3031.5,3468.5 ; D24.2@3000,5120.98 v1(3000,5190) ; R39.2@3038.5,3665.54 R39.2@3038.5,3670 3038.5,3718.5 3100.8,3780.8 3154.66,3780.8 3161.69,3787.82 3161.69,3835.17 3154.66,3842.2 3060.6,3842.2 Q5.2@3037.4,3819 2996.4,3860 2938.4,3860 Q6.2@2897.4,3819 2856.4,3860 2810,3860 2798.1,3848.1 2798.1,3810 ; v1(3050,1650) 3030,1650 2888.5,1791.5 2835.54,1791.5 ; D26.2@3100,5310.12 3100,5241.5 R82.1@3130,5211.5 R84.1@3210,5211.5 3240,5241.5 R83.1@3240,5348.5 3251.5,5360 v1(3290,5360) ; JY5.1@3230.79,3680 3234.97,3680 3339.44,3575.54 D52.1@3339.44,3569.63 D52.2@3376.84,3569.63 D52.3@3414.24,3569.63 ; Q40.2@3268.35,2188.43 3268.35,2274.1 R146.1@3262.44,2280 3262.44,2280.98 3308.51,2327.05 3308.51,2413.5 3349.45,2454.45 R145.1@3349.45,2455.43 3349.45,2456.42 3402.53,2509.5 3448,2509.5 3503.82,2565.31 3504.8,2565.31 3518.5,2579.02 C4.2@3518.5,2580 ; R151.1@3368,4690.55 3456.97,4690.55 3509.02,4638.5 C67.2@3510,4638.5 3510,4631.49 C60.2@3570,4571.5 3571.5,4570 v1(3620,4570) 3658.5,4570 C61.2@3660,4571.5 ; C50.2@3570,4378.5 C53.2@3660,4378.5 3688.51,4350 C59.2@3728.5,4350 3727.01,4348.5 v1@3727.01,4310 ; v1(3630,4760) 3650,4760 C89.2@3650,4701.5 C88.2@3720,4701.5 R73.1@3790,4701.5 ; C58.2@3727.01,4260 v1@3727.01,4309.53 ; v1@3730,4310 v1(3730.47,4309.53) ; JP11.5@3880,5360 TP5.1@3880,5430 ; C57.2@3890,4451.5 3920,4451.5 3921.5,4450 v1(3950,4450) 3998.5,4450 C56.2@4000,4451.5 ; C55.2@3941.5,4560 C54.2@3941.5,4630 3950,4638.5 v1(3950,4710) ; D53.2@4231.97,5302.25 4242.52,5302.25 4254.34,5314.07 4256.43,5314.07 4368.58,5426.22 SW1.4@4368.58,5427.95 ; SW1.3@4368.58,5172.05 4368.58,5111.42 4430,5050 D10.2@4469.02,5050 4473.7,5050 4500.5,5076.8 4500.5,5140.5 4520.47,5160.47 LA7.8@4532.76,5160.47 ; U9.2@4466.29,4513.13 4472.29,4507.13 4499.09,4507.13 4506.68,4499.54 v2@4520.21,4499.54 ; v2@4521.07,4498.69 4538.02,4481.73 4568.27,4481.73 U9.5@4574.27,4475.73 4654.38,4475.73 C87.2@4660.28,4481.63 ; v2(4564.39,4728.5) 4569.18,4723.72 4569.18,4709.17 4586.57,4691.78 4588.66,4691.78 4600.43,4680 D55.2@4610.98,4680 ; C182.2@4688.5,2915.42 4690,2916.92 BT1.-@4690,3002.99 4691.5,3001.5 4984.64,3001.5 5015.34,3032.2 5064.66,3032.2 5095.36,3001.5 C43.2@5220,3001.5 ; Q11.2@4724.8,1560 C15.2@4788.34,1560 ; C15.2@4782.36,1554.65 C15.2@4787.01,1550 ; v1(4782.52,1956.14) C6.1@4782.52,2004.65 ; C7.2@4844.57,1818.51 C18.2@4844.57,1748.51 4844.57,1704.1 v1(4845.51,1703.15) C8.2@4845.51,1644.65 4845.51,1608.5 C15.2@4787.01,1550 ; R173.2@4858.5,1250 4858.5,1251.5 4787.01,1322.99 R24.1@4787.01,1340 C16.2@4787.01,1410 R23.1@4787.01,1480 C15.2@4787.01,1550 ; C25.2@5011.5,2730 v1(5100,2730) ; NT1.2@5015.44,1061.56 5033.88,1080 v1(5040,1080) ; C69.1@5104.09,2165.75 v1(5150,2165.75) C73.1@5194.09,2165.75 C76.1@5264.09,2165.75 ; C9.2@5240,1450 5240,1518.5 C10.1@5241.5,1520 v1(5241.5,1582.13) 5250,1590.63 C21.2@5250,1764.65 C22.2@5250,1834.65 C19.2@5250,1904.65 C20.2@5250,1974.65 v1(5250,2080)
  Bottom Layer w20: LA8.8@516.14,4595.55 541.69,4570 ; D45.2@603.46,4647.8 v1@645.03,4647.8 ; v1(628.5,4800) D56.2@670.98,4800 ; D58.2@1673.28,5026.13 v1@1673.28,5057.22 ; v1(2370,1540) C109.2@2370,1587.01 ; C4.2@3518.5,2580 R35.1@3518.5,2650 R33.2@3518.5,2720 R30.2@3518.5,2790 ; C27.2@3842.99,2455.47 3891.5,2503.98 v1(3891.5,2540) C3.2@3891.5,2580 R20.2@3891.5,2650 R21.2@3891.5,2720 R22.1@3891.5,2790 3911.93,2769.57 3910,2767.64 v1(3910,2750)
  Bottom Layer w30: v1(1427.8,4767.8) 1430,4770 TP19.1@1510,4770 ; v1(2771.5,3105) 2806.5,3140 C5.2@2860,3140 ; C5.2@2865,3136.85 C65.2@2935,3136.85 ; R38.2@2880,3468.5 C14.2@2960,3468.5 ; C46.2@3040,2790 v1(3085,2790) C45.2@3130,2790 ; C177.2@3048.51,2478.5 C28.2@3048.51,2618.5 3048.51,2648.51 v1(3083.5,2683.5) ; U18.2@3111.64,3175 3114.34,3172.29 3167.71,3172.29 C64.2@3190,3150 v1(3231.25,3150) 3231.25,3161.25 TP10.1@3270,3200 ; R90.1@3401.5,3128.5 3443.49,3170.5 3456.36,3170.5 3479.5,3193.64 3479.5,3226.36 3437.36,3268.51 C47.2@3401.5,3268.51 ; v2@3810,2300 3842.99,2332.99 C26.2@3842.99,2385.47 C27.2@3842.99,2455.47
  Bottom Layer w40: v2(4030,2060) 4040,2070 R46.2@4040,2110
  Bottom Layer w100: v2@540,1310 540,1050 710,880 710,720 795.5,634.5 ; 795.5,579.14 795.5,624.5 ; 795.5,659.14 869.14,585.5 ; 869.14,515.5 1175.5,515.5 1310,650 1954.64,650 ; 1890,790 1890,720 1890.5,719.5 1890.5,714.14 1954.64,650 ; v2(3430,1250) 3430,1180 3650,960 ; v2(4860,960) v2(4820,960) v2(4780,960) v2(4740,960) 4700,920 3610,920 3340,650 1954.64,650
  other v1: 3290,1870 3160,2114.12 4190,2490 4250,2490 4250,2550 4310,2550 4370,2550 3500,2680 3020,3460 3080,3850 2300,4550
  other v2: 650,150 1870,750 1910,750 4720,760 4760,760 4800,760 4840,760 1870,790 1910,790 4740,800 4780,800 4820,800 4860,800 1870,830 1910,830 4720,840 4760,840 4800,840 4840,840 1870,870 4740,880 4780,880 4820,880 4860,880 4720,920 4760,920 4800,920 4840,920 4720,1000 4760,1000 4800,1000 4840,1000 3240,1240 3270,1250 3310,1250 3390,1250 510,1280 550,1280 590,1280 630,1280 670,1280 710,1280 750,1280 3250,1280 3290,1280 3330,1280 3370,1280 3410,1280 490,1320 530,1320 570,1320 610,1320 650,1320 690,1320 730,1320 3890,1520 3940,1520 3990,1520 4040,1520 4090,1520 4140,1520 4190,1520 4050,2020 4070,2060 3990,2068.5 3760,2210 3820,2210 3760,2300 3820,2300 2300,3380 2350,3380 2260,3390 2250,3430 2300,3430 2350,3430 2260,3470 2300,3480 2350,3480 1900,4020 1950,4020 2000,4020 1850,4070 1900,4070 1950,4070 2000,4070
GND_MON: C51.2 C52.2 C63.2 C66.2 C77.2 C78.2 C79.1 C80.2 C81.2 C82.2 C83.2 C84.1 C86.2 LA5.5 R100.1 R101.1 TP33.1 U8.2 U8.10 | length 1726.1
  Top Layer w10: U8.2@5590.12,2222.24 5639.25,2222.24 C66.2@5670,2191.5 C63.2@5740,2191.5 C52.2@5810,2191.5 C51.2@5880,2191.5 5942.99,2128.5 C78.2@5970,2128.5 C77.2@6110,2128.5 R100.1@6180,2128.5 6180,2070 ; TP33.1@6169.53,1987.24 6169.53,2059.53 6180,2070 ; v1(6170,2810) 6170,2777.72 LA5.5@6210.47,2737.24 ; v1(6280,1970) 6180,2070
  Top Layer w20: U8.10@5590.12,2622.24 5649.53,2681.65 C84.1@5649.53,2777.24 5691.02,2818.74 C82.2@5734.1,2818.74 C83.2@5804.1,2818.74 C81.2@5874.1,2818.74 C80.2@5944.1,2818.74 C86.2@6014.1,2818.74 C79.1@6084.09,2818.74 6092.83,2810 v1(6170,2810)
GND_PROT: C32.- C33.- C34.2 C35.- C38.2 C72.2 C74.2 C75.2 D14.A D15.A D16.A D29.A Q16.2 Q17.2 R61.1 R63.1 R68.1 R69.2 R70.2 R94.2 R96.2 R107.2 R108.2 TP9.1 TP26.1 U11.3 U17.12 | length 3408.2
  Top Layer w10: v1(5720,4788.5) 5720,4726.61 C35.-@5736.61,4710 ; U17.12@5790,4450 5850,4450 v1(5860,4460) ; v1(5880,4298.5) 5908.5,4270 C38.2@5938.5,4270
  Bottom Layer w10: v1(5370,5220) 5358.66,5231.34 U11.3@5358.66,5250 5558.5,5250 R107.2@5580,5228.5 ; R70.2@5481.5,4270 5481.5,4340 R94.2@5490,4348.5 C74.2@5570,4348.5 5570,4330 5640,4260 5760,4260 5790,4290 R63.1@5790,4320 5811.5,4298.5 v1(5880,4298.5) R96.2@5940,4298.5 R69.2@6010,4298.5 C75.2@6080,4298.5 ; C72.2@5681.5,4670 R108.2@5681.5,4750 v1(5720,4788.5) ; TP9.1@6220,4940 6300,4860 TP26.1@6350,4860
  Bottom Layer w20: C34.2@5410,4938.5 5496.93,4938.5 C32.-@5500,4941.57 5551.57,4890 5878.43,4890 C33.-@5930,4941.57 ; D16.A@5800,4960 5911.57,4960 C33.-@5930,4941.57 ; v1(6390,4480) 6421.6,4480 Q16.2@6432.6,4491 6432.6,4425.9 R61.1@6438.5,4420 6438.5,4401.5 6501.5,4338.5 R68.1@6501.5,4330 6501.5,4264.9 Q17.2@6507.4,4259 ; D15.A@6710,4850 D14.A@6500,4850 6410,4940 TP9.1@6220,4940 6200,4960 D29.A@6120,4960 6101.57,4941.57 C33.-@5930,4941.57
GT0: Q1.4 U1.2 | length 3216
  Top Layer w10: Q1.4@1768.94,895 v1(1810,895) ; v1(3770,2588) 3798.02,2616.02 U1.2@3824.17,2616.02
  Bottom Layer w10: v1(1810,895) 1853,938 2765.88,938 3270.5,1442.63 3270.5,1627 3489.26,1845.76 3489.26,2425.98 3613.28,2550 3730,2550 3768,2588 v1(3770,2588)
GT1: Q1.2 U1.4 | length 3461.8
  Top Layer w10: Q1.2@1768.94,795 1805,795 v1(1810,800) ; v1(3778,2541.4) 3778,2542 3761.5,2558.5 3757.78,2558.5 3740.5,2575.78 3740.5,2642.22 3765.49,2667.2 U1.4@3824.17,2667.2
  Bottom Layer w10: v1@1815,795 v1(1810,800) 1810,860 1815.5,865.5 1822.22,865.5 1839.5,882.78 1839.5,889.5 1870,920 2771.92,920 3291.72,1439.8 3291.72,1620.5 3509.5,1838.28 3509.5,2422.18 3617.32,2530 3789.4,2530 v1(3778,2541.4)
GT2: Q2.2 U1.6 | length 3318
  Top Layer w10: v1(1965,845) Q2.2@2011.06,845 ; v1(3760,2500) 3723.5,2536.5 3723.5,2705.22 3747.78,2729.5 3772.22,2729.5 3783.33,2718.39 U1.6@3824.17,2718.39
  Bottom Layer w10: v1(1965,845) 2023,903 2778.96,903 3320,1444.04 3320,1613.61 3526.5,1820.11 3526.5,2415.14 3620.86,2509.5 3732.22,2509.5 3740.86,2500.86 3759.14,2500.86 v1(3760,2500)
GT3: Q2.4 U1.10 | length 3353.4
  Top Layer w10: v1(1965,745) Q2.4@2011.06,745 ; U1.10@3595.83,2743.98 3599.74,2747.89 3692.11,2747.89 3706.5,2733.5 3706.5,2493.5 v1(3720,2480)
  Bottom Layer w10: v1(1965,745) 2106,886 2786,886 3341.21,1441.21 3341.21,1517.07 3340.5,1517.78 3340.5,1600 3547.41,1806.91 3547.41,2412.01 3624.9,2489.5 3692.22,2489.5 3701.72,2480 v1(3720,2480)
GT4: Q3.2 U1.12 | length 2027.3
  Top Layer w10: Q3.2@3355,1148.94 v1(3355,1195) ; U1.12@3595.83,2692.8 3645.49,2692.8 3649.4,2688.89 3661.11,2688.89 3686.5,2663.5 3686.5,2466.5 v1(3680,2460)
  Internal 2 w10: v1(3355,1195) 3475,1195 3564.5,1284.5 3564.5,1494.52 3490,1569.02 3420.98,1569.02 v1(3410,1580)
  Bottom Layer w10: v1(3410,1580) 3410,1627 3564.41,1781.41 3564.41,2402.33 3622.08,2460 v1(3680,2460)
GT5: Q3.4 U1.15 | length 2033.6
  Top Layer w10: Q3.4@3255,1148.94 v1(3255,1195) ; U1.15@3595.83,2616.02 3653.98,2616.02 3669.5,2600.5 3669.5,2567.78 3640,2538.28 v1(3640,2430)
  Internal 2 w10: v1(3255,1195) 3290,1160 3480,1160 3581.5,1261.5 3581.5,1271.8 3585.5,1275.8 3585.5,1514.74 3490.24,1610 v1(3450,1610)
  Bottom Layer w10: v1(3450,1610) 3583,1743 3583,2395.33 3602.67,2415 3625,2415 v1(3640,2430)
HVAUX.DEMB: D10.1 JY6.15 Q34.1 R181.2 TP14.1 U15.40 | length 8075.8
  Top Layer w10: v1(3460,3000) 3450.5,3009.5 3450.5,3160.5 3469.5,3179.5 3469.5,3628.38 3215.27,3882.61 3215.27,3923.55 3249.5,3957.78 3249.5,3982.22 3224.73,4006.99 3224.73,4370.72 3234.51,4380.5 3242.22,4380.5 3259.5,4397.78 3259.5,4422.22 3210,4471.72 3210,5000 3270,5060 3550,5060 TP14.1@3660,5170 3710.5,5119.5 3732.22,5119.5 3780.5,5071.22 3780.5,5003.54 3798.06,4985.99 3798.06,4802.55 3789.84,4794.34 U15.40@3789.84,4706.38 ; v1(4290,5070) 4290,5050 4320.5,5019.5 4320.5,4997.78 4500,4818.28 4500,4670 JY6.15@4800,4370
  Bottom Layer w10: R181.2@2380,1852.99 2374.09,1858.9 Q34.1@2309,1858.9 2309,1837.19 2273.38,1801.57 2273.38,1766.63 2280.41,1759.6 2355.05,1759.6 2355.34,1759.3 2404.65,1759.3 2409.35,1764 2676.6,1764 2720.6,1720 2935.96,1720 3035.46,1620.5 3062.22,1620.5 3090,1648.28 3090,1951.67 2961.55,2080.12 2959.67,2080.12 2910,2129.79 2910,2827.88 2952.69,2870.56 2952.69,2992.69 2986.5,3026.5 3029.26,3026.5 3035.76,3020 3454.24,3020 3460.74,3013.5 3460,3012.76 v1(3460,3000) ; TP14.1@3660,5170 3680,5150 4149.17,5150 4172.59,5126.58 4233.42,5126.58 v1(4290,5070) 4370,5070 4427.4,5012.6 D10.1@4469.02,5012.6
HVAUX.E\N\: Q31.1 R166.1 U15.27 | length 5446.2
  Top Layer w10: U15.27@4006.38,4529.21 4007.17,4530 4078.54,4530 4079.6,4531.06 4159.34,4531.06 4167.78,4539.5 4220.5,4539.5 4246.5,4513.5 4246.5,4410.74 4150,4314.24 4150,4158.08 4116.25,4124.33 4116.25,3976.05 4076.5,3936.3 4076.5,3815.96 4099.5,3792.96 4099.5,3607.78 4054.04,3562.32 4054.04,3537.78 4089.5,3502.32 4089.5,3409.5 v1(4070,3390)
  Bottom Layer w10: Q31.1@2153.65,1897.25 2157.4,1893.5 2157.4,1843.09 R166.1@2151.5,1837.19 2151.5,1836.2 2240.7,1747 2268.96,1747 2273.36,1742.6 2348,1742.6 2348.3,1742.3 2411.7,1742.3 2416.4,1747 2669.56,1747 2735.86,1680.7 2824.66,1680.7 2878.36,1627 2965.28,1627 2977.78,1639.5 2992.42,1639.5 3028.42,1603.5 3069.26,1603.5 3110,1644.24 3110,1955.71 2968.59,2097.12 2966.72,2097.12 2932,2131.83 2932,2825.83 2973,2866.83 2973,2984.72 2997.78,3009.5 3022.22,3009.5 3034.72,2997 3421.28,2997 3447.78,2970.5 3482.22,2970.5 3559.5,3047.78 3559.5,3061.22 3577.78,3079.5 3577.78,3147.78 3699.5,3269.5 3730.1,3269.5 3747.6,3287 3800.33,3287 3803.33,3290 4000,3290 4070,3360 v1(4070,3390)
HVAUX.FC0: D55.6 JY6.14 R141.2 R152.2 RA3.7 | length 2168.4
  Top Layer w10: v1(3710,4010) 3712.87,4012.87 3712.87,4081.53 RA3.7@3715.75,4084.41 ; v1@4430,4719.33 4430,4472.76 v1(4490,4412.76) 4490,4339.03 ; R141.2@4442.99,4339.03 4490,4339.03 ; R152.2@4537.01,4339.03 4490,4339.03
  Bottom Layer w10: v1(3710,4010) 3716.76,4010 3736.26,4029.5 3784.74,4029.5 3833.74,3980.5 3882.22,3980.5 3912.22,4010.5 4012.22,4010.5 4107.34,4105.62 4107.34,4261.38 4192.46,4346.5 4210.34,4346.5 4278.72,4414.87 4844.87,4414.87 JY6.14@4900,4470 ; v1(4430,4720) 4431.3,4718.7 4507.72,4718.7 D55.6@4509.02,4717.4
HVAUX.FC1: D55.4 JY6.16 RA3.8 U28.3 | length 5281.5
  Top Layer w10: v1(3150,4070) 3150,4260.46 3130.27,4280.18 3130.27,4471.85 3150,4491.57 v1(3150,4690) ; RA3.8@3747.24,4084.41 3747.24,4019.52 3760,4006.76 v1(3760,4000) ; v1@4470,4620 4480,4610 4480,4471.34 v1(4569.33,4382.01)
  Bottom Layer w10: U28.3@1117.98,4859.97 1159.97,4859.97 1191.64,4891.64 1243.7,4891.64 1249.09,4897.04 1337.74,4897.04 1376.67,4858.11 1527.85,4858.11 1705.08,4680.88 3140.88,4680.88 v1(3150,4690) ; v1(3150,4070) 3278.88,4070 3288.38,4079.5 3410.5,4079.5 3483.5,4006.5 3671.78,4006.5 3697.78,3980.5 3733.74,3980.5 3753.24,4000 v1(3760,4000) 3796.5,3963.5 3889.26,3963.5 3906.26,3980.5 4006.26,3980.5 4307.76,4282 4569.18,4282 ; v1(4470,4618.28) 4492.98,4641.26 4507.68,4641.26 D55.4@4509.02,4642.6 ; v1(4569.33,4382.01) 4569.33,4282.16 4569.18,4282 ; JY6.16@4900,4370 4812,4282 4569.18,4282
HVAUX.ISET: Q38.1 R196.2 U15.39 | length 5116.9
  Top Layer w10: v1(3300,5020) 3336.5,4983.5 3336.5,4750.74 3313.5,4727.74 3313.5,4303.22 3290,4279.72 3290,3981.72 3309.5,3962.22 3309.5,3937.78 3300.5,3928.78 3300.5,3821.42 3486.5,3635.42 3486.5,3066.5 v1(3480,3060) ; U15.39@3809.53,4706.38 3811.01,4707.86 3811.01,4791.47 3815.06,4795.51 3815.06,4993.03 3809.53,4998.56 3809.53,5049.53 v1(3810,5050)
  Bottom Layer w10: Q38.1@2659,1867.4 2659,1861 R196.2@2728.5,1791.5 2760.19,1823.18 2843.18,1823.18 2867.8,1847.8 2867.8,1899.62 2868.1,1899.91 2868.1,1961.09 2881.88,1974.87 2947.47,1974.87 2954.5,1981.9 2954.5,2039.09 2947.47,2046.12 2945.59,2046.12 2869,2122.71 2869,2841.12 2918.69,2890.81 2918.69,2929.22 2918.69,3028.69 2950.5,3060.5 3043.34,3060.5 3047.84,3056 3434.08,3056 3438.08,3060 v1(3480,3060) ; v1(3300,5020) 3309.5,5029.5 3582.22,5029.5 3585.22,5026.5 3746.3,5026.5 3769.8,5050 v1(3810,5050)
HVAUX.UART_A2P: D45.3 D45.4 JY6.12 LA8.6 R174.1 RA5.2 | length 5704.5
  Top Layer w10: RA5.2@3925.75,4875.59 v1(3925.75,4935.75)
  Bottom Layer w10: LA8.6@523.27,4658.54 LA8.6@516.14,4658.54 518.55,4660.95 544.92,4660.95 569.02,4685.04 603.3,4685.04 D45.3@603.46,4685.2 D45.4@705.42,4685.2 705.58,4685.04 711.5,4690.96 711.5,4868.74 739.34,4896.58 869.74,4896.58 885.63,4912.47 885.63,4955.77 891.49,4961.63 949.23,4961.63 960.86,4950 960.86,4929.95 993.81,4897 1048.75,4897 1079.98,4928.23 1079.98,4951.56 1139.92,5011.5 1318.5,5011.5 1450,4880 1540,4880 1722.12,4697.88 2851.92,4697.88 2880.5,4726.46 2880.5,4776.36 2990.64,4886.5 3323.04,4886.5 3332.04,4877.5 3678.66,4877.5 3686.66,4869.5 3859.5,4869.5 v1(3925.75,4935.75) 3932.51,4935.75 3946.76,4921.5 3958.49,4921.5 3974.28,4921.5 3974.59,4921.19 3982.85,4921.19 4013.54,4890.5 4184.75,4890.5 4230.25,4936 4576.2,4936 4583.7,4943.5 4731.37,4943.5 4760,4914.87 4918.59,4914.87 4977,4856.46 4977,4647 JY6.12@4900,4570 ; D45.4@717.2,4690.04 777.17,4750 R174.1@847.13,4750
HVAUX.UART_P2A: D45.1 D45.6 JY6.10 LA8.7 R212.1 RA5.1 | length 5064.8
  Top Layer w10: v1(3250,4600) 3249.5,4600.5 3249.5,4839.5 v1(3250,4840)
  Bottom Layer w10: LA8.7@516.14,4627.05 541.69,4627.05 558.34,4610.4 D45.1@603.46,4610.4 D45.6@705.42,4610.4 770.4,4610.4 818.54,4658.54 R212.1@847.76,4658.54 847.76,4657.56 889.93,4615.39 1165.39,4615.39 1199.5,4649.5 1282.22,4649.5 1289.22,4642.5 2081.43,4642.5 2108.43,4615.5 2642.53,4615.5 2687.53,4570.5 3080.54,4570.5 3110.04,4600 v1(3250,4600) ; v1(3250,4840) 3279.5,4869.5 3315.99,4869.5 3324.99,4860.5 3671.61,4860.5 3679.61,4852.5 3824.15,4852.5 3836.65,4840 3920,4840 v1@3967.03,4887.03 ; v1(3962.06,4892) 3968,4892 3986.5,4873.5 4192.46,4873.5 4237.96,4919 4583.24,4919 4590.74,4926.5 4680.04,4926.5 4781.41,4825.13 4918.59,4825.13 4960,4783.71 4960,4730 JY6.10@4900,4670
HVAUX.VSET: Q36.1 R186.2 U15.28 | length 4062.1
  Top Layer w10: v1(3540,3100) v1(3540,3310) ; U15.28@4006.38,4548.9 4153.14,4548.9 4160.74,4556.5 4227.54,4556.5 4263.5,4520.54 4263.5,4403.7 4170,4310.2 4170,4154.04 4133.25,4117.29 4133.25,3969.01 4093.5,3929.26 4093.5,3823 4116.5,3800 4116.5,3600.74 4090,3574.24 4090,3556.46 v1(4083.54,3550)
  Bottom Layer w10: R186.2@2961.5,1861.5 Q36.1@2961.5,1926.59 ; Q36.1@2967.4,1932.5 2971.5,1936.6 2971.5,2046.13 2954.51,2063.12 2952.63,2063.12 2886,2129.75 2886,2827.92 2935.69,2877.6 2935.69,2936.26 2935.69,3015.69 2963.5,3043.5 3036.3,3043.5 3040.8,3039 3459.28,3039 3467.78,3030.5 3492.22,3030.5 3540,3078.28 v1(3540,3100) ; v1(3540,3310) 3615.96,3310 3626.46,3320.5 3708.98,3320.5 3858.98,3470.5 3902.22,3470.5 3981.72,3550 v1(4083.54,3550)
HVX_1V65: R206.2 R210.1 U27.1 U27.2 | length 405.2
  Bottom Layer w10: R206.2@1550,1438.5 1550,1400 1610,1340 1716.22,1340 1739.92,1363.7 1739.92,1390.51 U27.2@1742.8,1393.39 U27.1@1768.39,1393.39 1835.12,1393.39 R210.1@1848.5,1380
HVX_CM: R191.1 R198.1 U23.10 | length 671.8
  Top Layer w10: U23.10@2316.14,2295.55 v1(2375.55,2295.55)
  Internal 2 w10: v1(2375.55,2295.55) 2375.55,2625.55 v1(2380,2630)
  Bottom Layer w10: v1(2375.55,2295.55) 2391.5,2311.5 R191.1@2391.5,2350 ; v1(2380,2630) 2538.5,2630 R198.1@2578.5,2670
